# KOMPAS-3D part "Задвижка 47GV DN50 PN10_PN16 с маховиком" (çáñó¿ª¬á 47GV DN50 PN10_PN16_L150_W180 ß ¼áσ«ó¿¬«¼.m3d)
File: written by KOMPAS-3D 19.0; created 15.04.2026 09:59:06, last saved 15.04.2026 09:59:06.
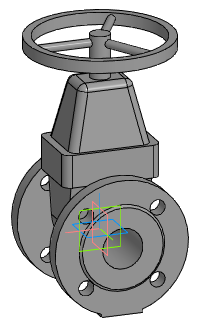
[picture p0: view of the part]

Document properties: Автор: Евгений; Полное имя файла: Z:\3.Личные\kachalov\3d для проектировщиков\2.1 Тип 47GV, 47GV.Z\Задвижка 47GV_DN40-DN600\stp_Задвижка 47GV\Задвижка 47GV DN50 PN10_PN16_L150_W180 с маховиком.m3d

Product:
- Part/product: Задвижка 47GV DN50 PN10_PN16 с маховиком

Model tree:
1. Операция без истории:1  (labels: Задвижка 47GV DN50 PN10_PN16 с маховиком)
